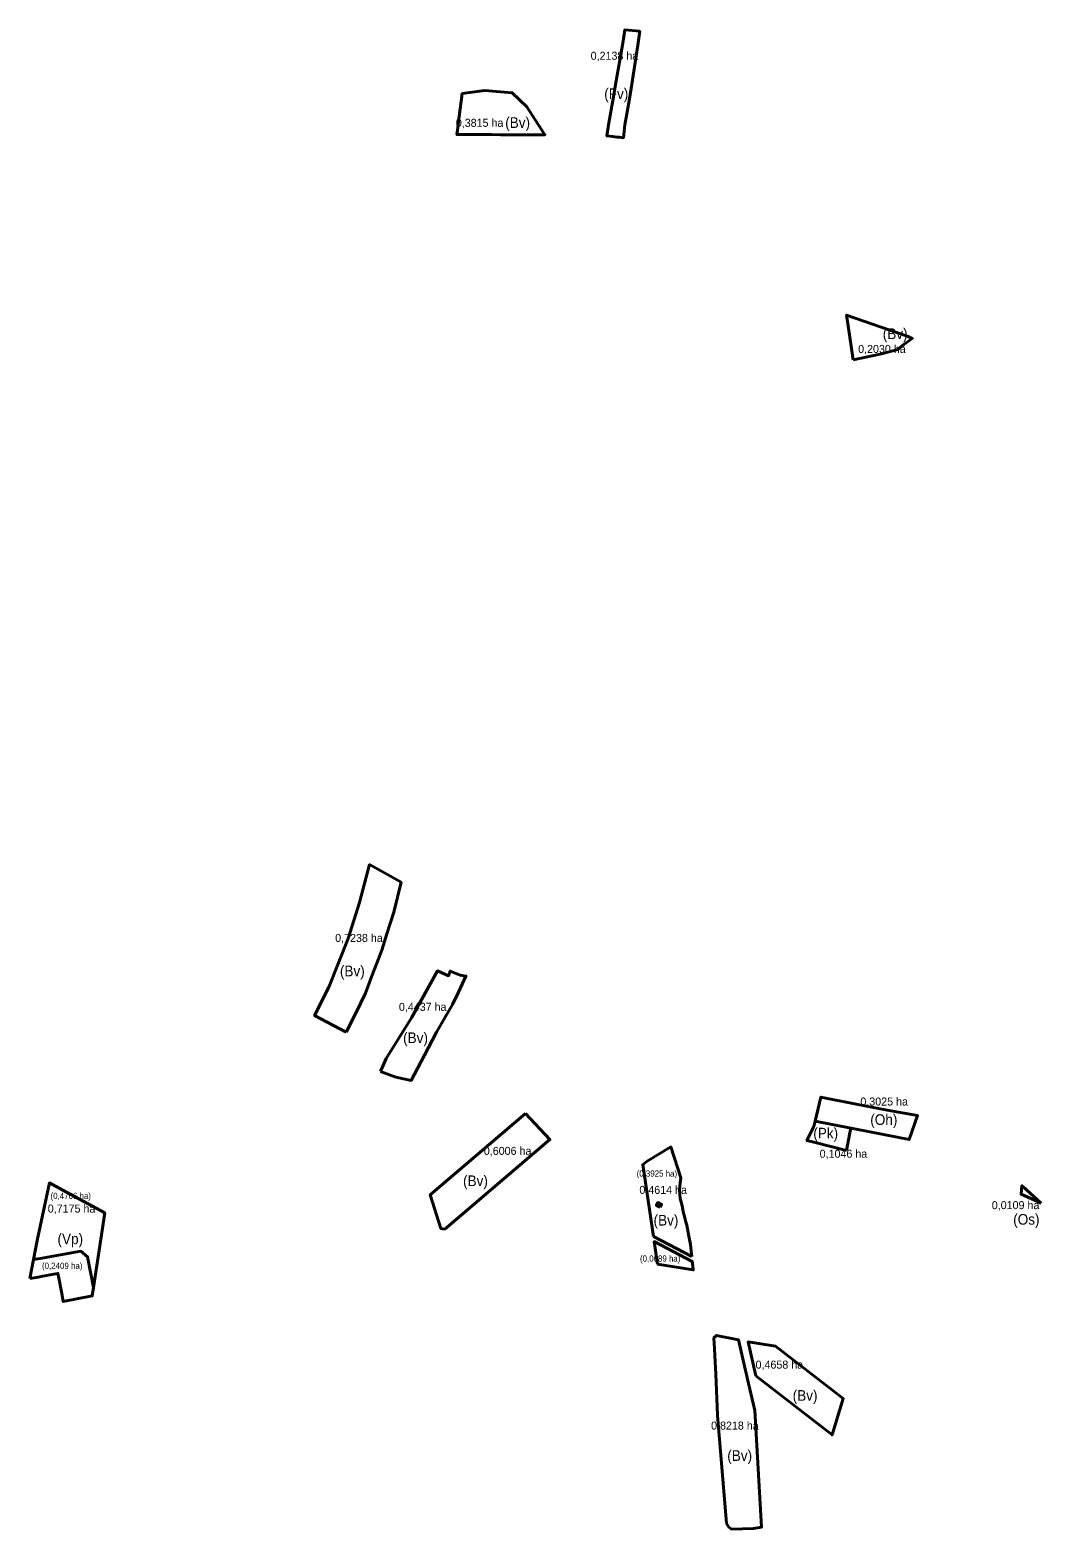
# Model space of a CAD drawing. Extents: x -555089 to -553952, y -1185789 to -1184103.
import ezdxf
from ezdxf.enums import TextEntityAlignment as Align

# ---------------------------------------------------------------- set-up
doc = ezdxf.new("R2010")
doc.units = 0
doc.header["$LTSCALE"] = 3.6
doc.layers.add('1', color=7, linetype='Continuous', lineweight=40)
doc.layers.add('2', color=7, linetype='Continuous', lineweight=40)
doc.layers.add('60', color=7, linetype='Continuous')
doc.layers.add('61', color=7, linetype='Continuous')

msp = doc.modelspace()

# ---------------------------------------------------------------- linework, layer by layer
at = {"layer": '1'}
msp.add_line((-554387.895, -1185459.701), (-554344.6, -1185481.98), dxfattribs=at)
for points in [[(-554415.38, -1184182.72), (-554413.02, -1184168.92), (-554405.62, -1184120.08), (-554403.37, -1184104.58), (-554420.12, -1184103.06), (-554422.41, -1184117.71), (-554430.77, -1184166.73), (-554433.24, -1184180.51), (-554438.09, -1184207.49), (-554440.16, -1184222.12), (-554434.03, -1184222.84), (-554428.6, -1184223.48), (-554426.63, -1184223.71), (-554421.69, -1184224.28), (-554419.97, -1184209.57)], [(-554733.51, -1185230.02), (-554730.2, -1185223.52), (-554717.59, -1185197.71), (-554711.77, -1185186.23), (-554704.88, -1185167.56), (-554699.12, -1185152.43), (-554693.52, -1185137.73), (-554687.65, -1185119.22), (-554679.93, -1185094.89), (-554679.52, -1185093.4), (-554671.85, -1185061.39), (-554707.18, -1185041.55), (-554718.485, -1185084.142), (-554731.329, -1185124.63), (-554753.057, -1185179.2), (-554769.052, -1185211.233)], [(-554694.99, -1185274.23), (-554688.42, -1185259.67), (-554660.04, -1185213.75), (-554630.97, -1185160.97), (-554618.25, -1185166.48), (-554616.48, -1185161.3), (-554605.12, -1185165.73), (-554598.76, -1185166.79), (-554607.1, -1185184.92), (-554613.87, -1185198.73), (-554631.94, -1185230), (-554645.24, -1185255.79), (-554660.25, -1185284.19), (-554677.59, -1185280.44)], [(-554531.777, -1185321.491), (-554638.923, -1185412.788), (-554627.182, -1185450.638), (-554622.556, -1185451.394), (-554504.308, -1185350.637)], [(-554380.43, -1185426.85), (-554378.73, -1185423.62), (-554382.8, -1185421.48), (-554384.5, -1185424.71)], [(-554383.322, -1185490.608), (-554343.144, -1185497.196), (-554343.59, -1185493), (-554344.16, -1185487.64), (-554387.061, -1185465.337)], [(-555089.21, -1185507), (-555085.125, -1185485.67), (-555077.651, -1185484.353), (-555031.815, -1185476.339), (-555024.403, -1185482.509), (-555017.806, -1185516.915), (-555019.241, -1185526.435), (-555051.7, -1185532.91), (-555053.44, -1185523.9), (-555056.79, -1185506.46), (-555057.82, -1185501.14), (-555062.21, -1185501.96), (-555074.79, -1185504.31), (-555079.88, -1185505.26), (-555084.52, -1185506.13)]]:
    msp.add_lwpolyline(points, close=True, dxfattribs=at)
for points in [[(-554535.41, -1184220.79), (-554526.4, -1184220.82), (-554519.59, -1184220.81), (-554509.93, -1184220.84), (-554530.2, -1184189.32), (-554546.63, -1184173.61), (-554577.52, -1184171.17), (-554602.96, -1184174.54), (-554607.39, -1184209.02), (-554608.27, -1184215.84), (-554608.89, -1184220.71), (-554597.59, -1184220.73), (-554570.19, -1184220.76)], [(-554570.19, -1184220.76), (-554559.89, -1184220.77), (-554535.41, -1184220.79)], [(-554205.92, -1185330.047), (-554207, -1185334.66), (-554207.96, -1185336.64), (-554215.313, -1185351.817), (-554207.47, -1185353.77), (-554170.793, -1185362.901)], [(-554170.793, -1185362.901), (-554167.012, -1185343.092), (-554166.009, -1185337.836), (-554205.92, -1185330.047)], [(-554344.6, -1185481.98), (-554345.29, -1185475.74), (-554346.15, -1185468.55), (-554348.02, -1185459.19), (-554350.5, -1185447.06), (-554351.77, -1185442.03), (-554353.02, -1185437.14), (-554354.3, -1185432.1), (-554355.39, -1185427.08), (-554356.48, -1185422.06), (-554357.86, -1185417.02), (-554358.24, -1185412.39), (-554358.55, -1185407.8), (-554358.1, -1185403.56), (-554357.73, -1185399.4), (-554357.24, -1185393.87), (-554368.27, -1185358.89), (-554394.81, -1185374.96), (-554398.64, -1185377.82), (-554399.867, -1185378.779), (-554387.895, -1185459.701)]]:
    msp.add_lwpolyline(points, dxfattribs=at)
at = {"layer": '2'}
for points in [[(-554163.2, -1184474.11), (-554169.02, -1184435.57), (-554170.7, -1184423.54), (-554101.44, -1184447.55), (-554096.79, -1184449.95), (-554106.24, -1184456.86), (-554113.17, -1184462.37), (-554133.03, -1184467.75)], [(-554205.92, -1185330.047), (-554100.379, -1185350.644), (-554090.82, -1185323.71), (-554124.84, -1185317.69), (-554160.01, -1185310.95), (-554199.59, -1185303)], [(-555031.815, -1185476.339), (-555024.403, -1185482.509), (-555017.806, -1185516.915), (-555005.1, -1185432.97), (-555052.93, -1185407.202), (-555067.367, -1185399.402), (-555081.04, -1185464.34), (-555085.125, -1185485.67), (-555077.651, -1185484.353)], [(-553951.92, -1185422.15), (-553972.449, -1185403.469), (-553973.359, -1185402.641), (-553974.35, -1185411.9)], [(-554305.651, -1185782.363), (-554303.28, -1185786.68), (-554300.2, -1185788.59), (-554275.27, -1185787.98), (-554266.32, -1185786.4), (-554273.88, -1185655.23), (-554282.43, -1185618.58), (-554282.94, -1185616.37), (-554284.34, -1185610.24), (-554292.21, -1185575.92), (-554316.867, -1185570.895), (-554319.852, -1185573.671), (-554319.21, -1185586), (-554318.84, -1185593.32), (-554317.73, -1185614.65), (-554316.26, -1185651.34), (-554315.85, -1185660.44)], [(-554272.647, -1185616.49), (-554281.413, -1185578.266), (-554250.477, -1185583.069), (-554174.425, -1185641.889), (-554187.013, -1185682.721)]]:
    msp.add_lwpolyline(points, close=True, dxfattribs=at)

# ---------------------------------------------------------------- texts
at = {"layer": '60', "width": 0.95}
for s, p in [('(Fv)', (-554429.716, -1184180.743)), ('(Bv)', (-554540.659, -1184213.207)), ('(Bv)', (-554115.973, -1184450.561)), ('(Bv)', (-554726.618, -1185167.146)), ('(Bv)', (-554655.508, -1185242.228)), ('(Oh)', (-554128.74, -1185334.233)), ('(Pk)', (-554194.127, -1185349.463)), ('(Bv)', (-554588.083, -1185403.023)), ('(Bv)', (-554373.794, -1185447.343)), ('(Os)', (-553968.412, -1185446.396)), ('(Vp)', (-555043.848, -1185468.374)), ('(Bv)', (-554217.312, -1185644.422)), ('(Bv)', (-554290.873, -1185712.043))]:
    msp.add_text(s, height=12, dxfattribs=at).set_placement(p, align=Align.CENTER)
at = {"layer": '61'}
for s, p in [('0,2138 ha', (-554431.76, -1184136.542)), ('0,3815 ha', (-554583.453, -1184211.931)), ('0,2030 ha', (-554130.887, -1184466.199)), ('0,7238 ha', (-554719.152, -1185128.486)), ('0,4437 ha', (-554647.419, -1185205.931)), ('0,3025 ha', (-554128.373, -1185312.39)), ('0,6006 ha', (-554551.926, -1185367.906)), ('0,1046 ha', (-554174.177, -1185371.102)), ('0,4614 ha', (-554376.932, -1185411.768)), ('0,7175 ha', (-555042.416, -1185432.786)), ('0,0109 ha', (-553980.564, -1185428.9)), ('0,4658 ha', (-554246.257, -1185608.239)), ('0,8218 ha', (-554296.287, -1185676.774))]:
    msp.add_text(s, height=9, dxfattribs=at).set_placement(p, align=Align.CENTER)
at = {"layer": '61', "width": 0.95}
for s, p in [('(0,3925 ha)', (-554384.025, -1185392.35)), ('(0,4766 ha)', (-555043.343, -1185417.48)), ('(0,0689 ha)', (-554380.313, -1185487.956)), ('(0,2409 ha)', (-555052.939, -1185496.066))]:
    msp.add_text(s, height=7, dxfattribs=at).set_placement(p, align=Align.CENTER)

doc.saveas('drawing.dxf')
